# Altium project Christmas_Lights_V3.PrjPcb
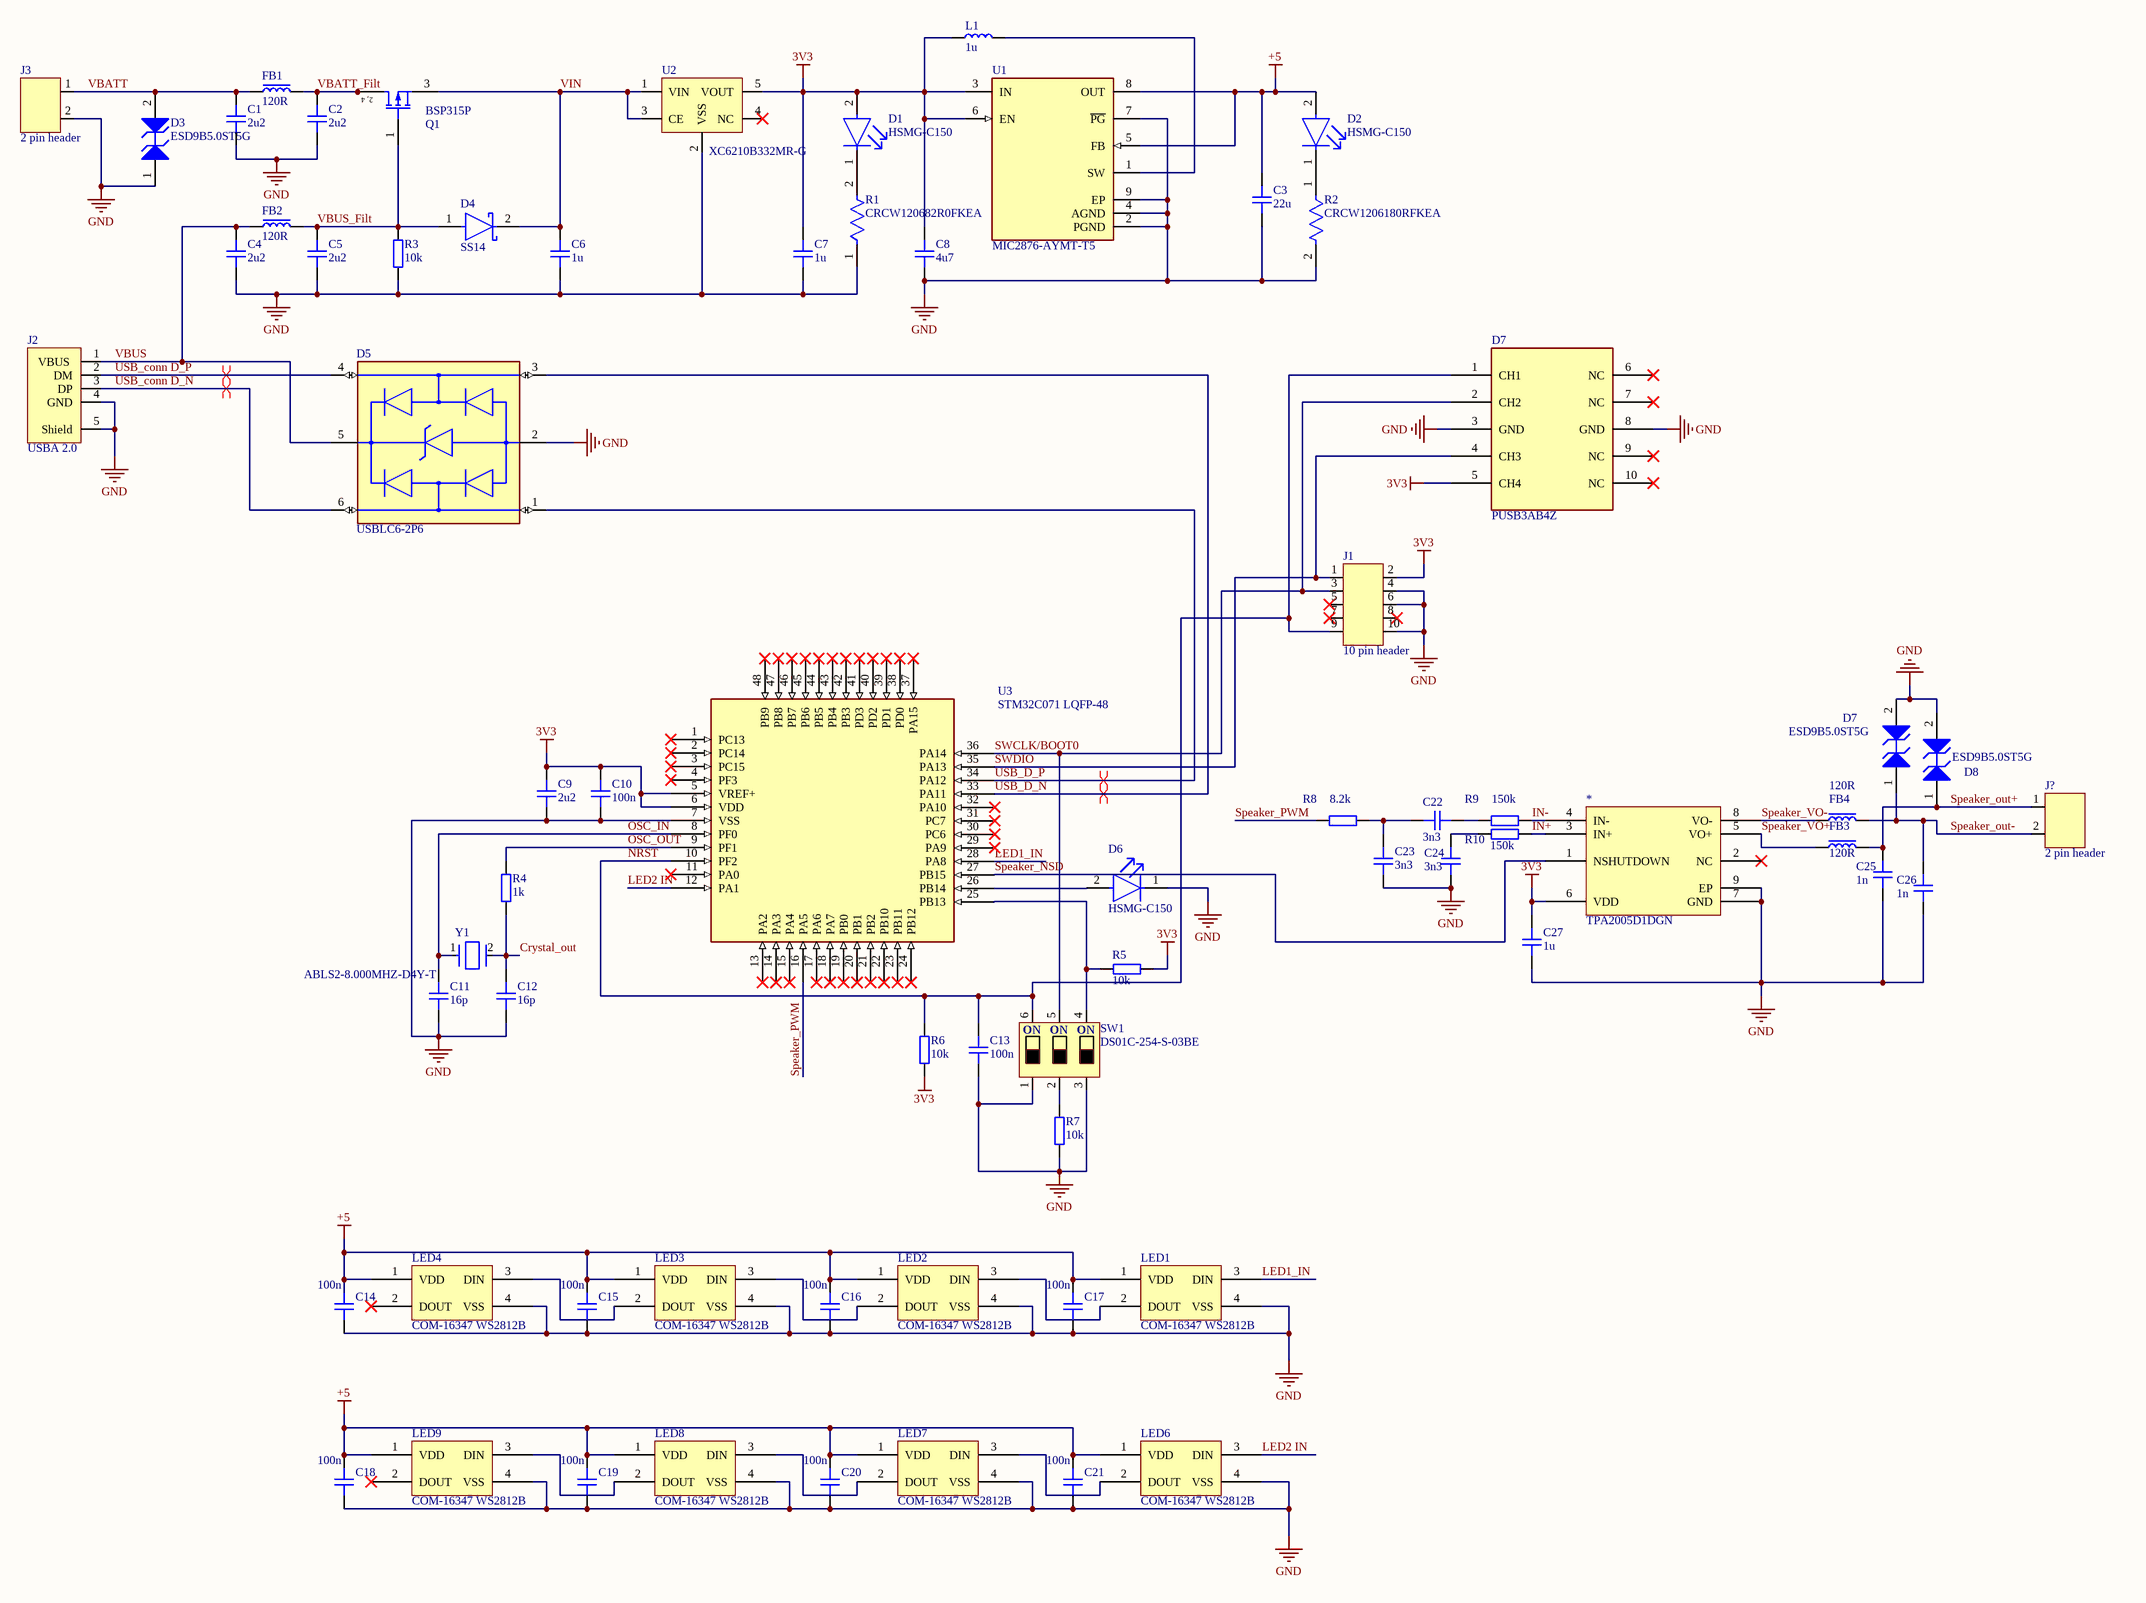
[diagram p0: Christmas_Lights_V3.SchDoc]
1 sheet, 70 parts. Net scope: global (net labels, ports and power ports of the same name join across sheets).
Board file: Christmas_Lights_V3.PcbDoc

## Sheet Christmas_Lights_V3.SchDoc
size A2; SheetNumber: 1; SheetTotal: 1

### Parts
(Parts that share a designator on the sheet are numbered #1, #2 ... from top to bottom, then left to right.)
*  TPA2005D1DGN  [TPA2005D1DGN]
C1  2u2  [CAP_0603]
C2  2u2  [CAP_0603]
C3  22u  [CAP_0805]
C4  2u2  [CAP_0603]
C5  2u2  [CAP_0603]
C6  1u  [CAP_0603]
C7  1u  [CAP_0603]
C8  4u7  [CAP_0603]
C9  2u2  [CAP_0603]
C10  100n  [CAP_0603]
C11  16p  [CAP_0603]
C12  16p  [CAP_0603]
C13  100n  [CAP_0603]
C14  100n  [CAP_0603]
C15  100n  [CAP_0603]
C16  100n  [CAP_0603]
C17  100n  [CAP_0603]
C18  100n  [CAP_0603]
C19  100n  [CAP_0603]
C20  100n  [CAP_0603]
C21  100n  [CAP_0603]
C22  3n3  [CAP_0603]
C23  3n3  [CAP_0603]
C24  3n3  [CAP_0603]
C25  1n  [CAP_0603]
C26  1n  [CAP_0603]
C27  1u  [CAP_0603]
D1  HSMG-C150  [FP-HSMG-C150-MFG]
D2  HSMG-C150  [FP-HSMG-C150-MFG]
D3  ESD9B5.0ST5G  [ONSC-SOD-923-2-514AB-01_V]
D4  SS14  [FP-403AE-MFG]
D5  USBLC6-2P6  [FP-SOT-666-MFG]
D6  HSMG-C150  [FP-HSMG-C150-MFG]
D7#1  PUSB3AB4Z  [SOT1176-1]
D7#2  ESD9B5.0ST5G  [ONSC-SOD-923-2-514AB-01_V]
D8  ESD9B5.0ST5G  [ONSC-SOD-923-2-514AB-01_V]
FB1  120R  [FB_0603]
FB2  120R  [FB_0603]
FB3  120R  [FB_0603]
FB4  120R  [FB_0603]
J1  10 pin header  [5x2 10 pin (1.27mm)]
J2  USBA 2.0  [USB A 87583 2010]
J3  2 pin header  [Screw connector]
J?  2 pin header  [Screw connector]
L1  1u  [IND_0603]
LED1  COM-16347 WS2812B  [COM-16347]
LED2  COM-16347 WS2812B  [COM-16347]
LED3  COM-16347 WS2812B  [COM-16347]
LED4  COM-16347 WS2812B  [COM-16347]
LED6  COM-16347 WS2812B  [COM-16347]
LED7  COM-16347 WS2812B  [COM-16347]
LED8  COM-16347 WS2812B  [COM-16347]
LED9  COM-16347 WS2812B  [COM-16347]
Q1  BSP315P  [INF-PG-SOT223_SC-73_L]
R1  CRCW120682R0FKEA  [FP-CRCW1206-e3-IPC_A]
R2  CRCW1206180RFKEA  [FP-CRCW1206-e3-IPC_C]
R3  10k  [RES_0603]
R4  1k  [RES_0603]
R5  10k  [RES_0603]
R6  10k  [RES_0603]
R7  10k  [RES_0603]
R8  8.2k  [RES_0603]
R9  150k  [RES_0603]
R10  150k  [RES_0603]
SW1  DS01C-254-S-03BE  [DS01C-254-S-03BE]
U1  MIC2876-AYMT-T5  [FP-TDFN22-8LD-PL-1-MFG]
U2  XC6210B332MR-G  [SOT25]
U3  STM32C071 LQFP-48  [LQFP-48]
Y1  ABLS2-8.000MHZ-D4Y-T  [FP-ABLS2-MFG]

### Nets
3V3: *.6(VDD) C7.2 C8.2 C9.2 C10.2 C27.2 D1.2(A) D7#1.5(CH4) J1.2 L1.1 R5.2 R6.2 U1.3(IN) U1.6(EN) U2.5(VOUT) U3.5(VREF+) U3.6(VDD)
+5: C3.2 C14.2 C15.2 C16.2 C17.2 C18.2 C19.2 C20.2 C21.2 D2.2(A) LED1.1(VDD) LED2.1(VDD) LED3.1(VDD) LED4.1(VDD) LED6.1(VDD) LED7.1(VDD) LED8.1(VDD) LED9.1(VDD) U1.5(FB) U1.8(OUT)
GND: *.7(GND) *.9(EP) C1.1 C2.1 C3.1 C4.1 C5.1 C6.1 C7.1 C8.1 C9.1 C10.1 C11.1 C12.1 C13.1 C14.1 C15.1 C16.1 C17.1 C18.1 C19.1 C20.1 C21.1 C23.2 C24.1 C25.1 C26.1 C27.1 D3.1(A1) D5.2(GND) D6.1(C) D7#1.3(GND) D7#1.8(GND) D7#2.2(A2) D8.2(A2) J1.4 J1.6 J1.10 J2.4(GND) J2.5(Shield) J3.2 LED1.4(VSS) LED2.4(VSS) LED3.4(VSS) LED4.4(VSS) LED6.4(VSS) LED7.4(VSS) LED8.4(VSS) LED9.4(VSS) R1.1 R2.2 R3.1 R7.2 SW1.1 SW1.3 U1.2(PGND) U1.4(AGND) U1.7(~{PG}) U1.9(EP) U2.2(VSS) U3.7(VSS)
Crystal_out: C12.2 R4.2 Y1.2
IN+: *.3(IN+) R10.2
IN-: *.4(IN-) R9.2
LED1_IN: LED1.3(DIN) U3.28(PA8)
LED2 IN: LED6.3(DIN) U3.12(PA1)
NRST: C13.2 D7#1.1(CH1) J1.9 R6.1 SW1.6 U3.10(PF2)
OSC_IN: C11.2 U3.8(PF0) Y1.1
OSC_OUT: R4.1 U3.9(PF1)
Speaker_NSD: *.1(NSHUTDOWN) U3.27(PB15)
Speaker_out+: C25.2 D8.1(A1) FB3.2 J?.1
Speaker_out-: C26.2 D7#2.1(A1) FB4.2 J?.2
Speaker_PWM: R8.1 U3.16(PA5)
Speaker_VO+: *.5(VO+) FB3.1
Speaker_VO-: *.8(VO-) FB4.1
SWCLK/BOOT0: D7#1.2(CH2) J1.3 SW1.5 U3.36(PA14)
SWDIO: D7#1.4(CH3) J1.1 U3.35(PA13)
USB_conn D_N: D5.6(I/O1) J2.3(DP)
USB_conn D_P: D5.4(I/O2) J2.2(DM)
USB_D_N: D5.3(I/O2) U3.33(PA11)
USB_D_P: D5.1(I/O1) U3.34(PA12)
VBATT: C1.2 D3.2(A2) FB1.1 J3.1
VBATT_Filt: C2.2 FB1.2 Q1.2(D) Q1.4(D)
VBUS: C4.2 D5.5(VBUS) FB2.1 J2.1(VBUS)
VBUS_Filt: C5.2 D4.1(A) FB2.2 Q1.1(G) R3.2
VIN: C6.2 D4.2(C) Q1.3(S) U2.1(VIN) U2.3(CE)
NetC22_1: C22.1 R9.1
NetC22_2: C22.2 C23.1 R8.2
NetC24_2: C24.2 R10.1
NetD1_1: D1.1(C) R1.2
NetD2_1: D2.1(C) R2.1
NetD6_2: D6.2(A) U3.26(PB14)
NetL1_2: L1.2 U1.1(SW)
NetLED1_2: LED1.2(DOUT) LED2.3(DIN)
NetLED2_2: LED2.2(DOUT) LED3.3(DIN)
NetLED3_2: LED3.2(DOUT) LED4.3(DIN)
NetLED6_2: LED6.2(DOUT) LED7.3(DIN)
NetLED7_2: LED7.2(DOUT) LED8.3(DIN)
NetLED8_2: LED8.2(DOUT) LED9.3(DIN)
NetR5_1: R5.1 SW1.4 U3.25(PB13)
NetR7_1: R7.1 SW1.2

Not connected (* = marked no-connect by the designer): * 2(NC)*; D7#1 6(NC)* 7(NC)* 9(NC)* 10(NC)*; J1 5* 7* 8*; LED4 2(DOUT)*; LED9 2(DOUT)*; U2 4(NC)*; U3 1(PC13)* 2(PC14)* 3(PC15)* 4(PF3)* 11(PA0)* 13(PA2)* 14(PA3)* 15(PA4)* 17(PA6)* 18(PA7)* 19(PB0)* 20(PB1)* 21(PB2)* 22(PB10)* 23(PB11)* 24(PB12)* 29(PA9)* 30(PC6)* 31(PC7)* 32(PA10)* 37(PA15)* 38(PD0)* 39(PD1)* 40(PD2)* 41(PD3)* 42(PB3)* 43(PB4)* 44(PB5)* 45(PB6)* 46(PB7)* 47(PB8)* 48(PB9)*

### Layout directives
differential pair: USB_conn D_N, USB_conn D_P, USB_D_N, USB_D_P

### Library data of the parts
C1 C2 C4-C27 = CAP_0603: Capacitor SMD 0603
C3 = CAP_0805: Capacitor SMD 0805
D1 D2 D6 = CMP-2000-05061-2: LED GREEN DIFFUSED 1206 SMD; Manufacturer: Broadcom; Led Orientation: Top View; Max Junction Temp: +95°C; Peak Emmision Wavelength: 570nm; Viewing Angle: 170°; Wavelength: 572nm; Reverse Voltage: 5V; Luminous Intensity: 15mcd; Forward Voltage: 2.2V; Power Dissipation: 65mW; Forward Current: 20mA
D3 D7#2 D8 = CMP-1063-00119-1: Transient Voltage Suppressor, Micro-Packaged Diode for ESD Protection, 2-Pin SOD-923, Pb-Free, Tape and Reel; Manufacturer: On Semiconductor; Number of Lines: 1; Direction: Bidirectional; V(BR) Min (V): 5.8; VRWM Max (V): 5
D4 = CMP-2000-04943-2: DIODE SCHOTTKY 40V 1A SMA; Manufacturer: ON Semiconductor; Peak Reverse Current: 0.2mA; Max Junction Temp: +125°C; Standoff Height: 0.05mm; Max Surge Forward Current: 40A
D5 = CMP-12225-000058-1: TVS DIODE 5.25V 17V SOT666; Min Breakdown Voltage: 6V; Power Line Protection: Yes; Element Configuration: Dual; Test Current: 1mA; Working Voltage: 5V; Number of Channels: 2; Max Reverse Leakage Current: 150nA; Direction: Unidirectional; Peak Pulse Current: 5A; Number of Elements: 1; Capacitance: 3.5pF
FB1-FB4 = FB_0603: Ferrite Bead SMD 0603
L1 = IND_0603: Inductor SMD 0603
Q1 = CMP-1099-00022-1: P-Channel SIPMOS Small-Signal-Transistor, -60 V VDS, -1.17 A ID, -55 to 150 degC, PG-SOT223 (SC-73), Reel, Green; Manufacturer: Infineon; ID (max): -1.17Â A; Polarity: P; VGS(th) (min): -1Â V; IDpuls (max): -4.68Â A; Pto t (max): 1.8Â W; QG: -5.2Â nC; Rth: 115Â K/W; Mode: Enhancement; Green: TRUE; RDS (on) (max): 800Â mOhm; VGS(th) (max): -2Â V; VDS (max): -60Â V
R1 = CMP-2003-02405-2: RES Thick Film, 82Ω, 1%, 0.25W, 100ppm/°C, 1206; Resistance: 82R; Max Power Dissipation: 250mW; Working Voltage: 200V
R2 = CMP-2003-01848-2: RES Thick Film, 180Ω, 1%, 0.25W, 100ppm/°C, 1206; Voltage Rating (DC): 200V; Resistance: 180R; Power Rating: 250mW
R3-R10 = RES_0603: Resistor SMD 0603
SW1 = DS01C-254-S-03BE: DIP Switch SPST 3 Positions Short Pins 2.54mm Pitch; Manufacturer: CUI Devices
U1 = CMP-06325-000017-1: IC REG BOOST ADJ 3.8A 8TDFN; Output Type: Adjustable; Max Input Voltage: 5.5V; Synchronous Rectifier: No; Number of Outputs: 1; Min Input Voltage: 2.5V; Switching Frequency: 2MHz; Output Configuration: Positive
Y1 = CMP-27762-001729-1: CRYSTAL 8.0000MHZ 18PF SMD; Series Resistance: 80R; Tolerance: 30ppm; Frequency: 8MHz; Operating Frequency: 8 MHz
